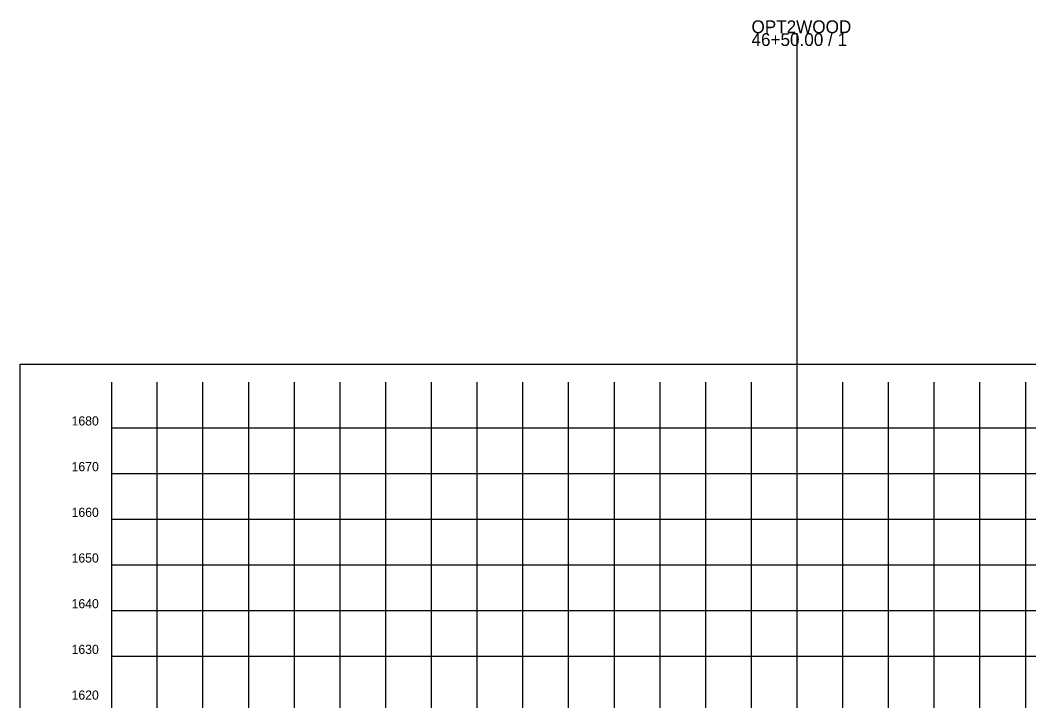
# Model space of a CAD drawing. Extents: x -26 to 2998798, y -429 to 819149.
# Drawn here: x 130 to 350.7, y 2089.2 to 2238.2 of the extents above; entities that cross this region are included whole.
import ezdxf

# ---------------------------------------------------------------- set-up
doc = ezdxf.new("R2010")
doc.units = 0
for name, color, linetype in [('DESIGN - SHEET - Corner Text', 7, 'Continuous'), ('DESIGN - SHEET - Light Grid', 7, 'Continuous'), ('DESIGN - SHEET - Linework', 7, 'Continuous'), ('DESIGN - SHEET - Plot Shape', 7, 'Continuous')]:
    doc.layers.add(name, color=color, linetype=linetype)

msp = doc.modelspace()

# ---------------------------------------------------------------- linework, layer by layer
at = {"layer": 'DESIGN - SHEET - Light Grid'}
msp.add_line((300, 2000), (300, 2235.37), dxfattribs=at)
at = {"layer": 'DESIGN - SHEET - Linework'}
for p, q in [((160, 1949), (160, 2159)), ((170, 1949), (170, 2159)), ((180, 1949), (180, 2159)), ((190, 1949), (190, 2159)), ((200, 1949), (200, 2159)), ((210, 1949), (210, 2159)), ((220, 1949), (220, 2159)), ((230, 1949), (230, 2159)), ((240, 1949), (240, 2159)), ((250, 1949), (250, 2159)), ((260, 1949), (260, 2159)), ((270, 1949), (270, 2159)), ((280, 1949), (280, 2159)), ((290, 1949), (290, 2159)), ((300, 1949), (300, 2159)), ((310, 1949), (310, 2159)), ((320, 1949), (320, 2159)), ((330, 1949), (330, 2159)), ((340, 1949), (340, 2159)), ((350, 1949), (350, 2159)), ((150, 2149), (450, 2149)), ((150, 2139), (450, 2139)), ((150, 2129), (450, 2129)), ((150, 2119), (450, 2119)), ((150, 2109), (450, 2109)), ((150, 2099), (450, 2099))]:
    msp.add_line(p, q, dxfattribs=at)
msp.add_lwpolyline([(150, 2159), (150, 1949), (450, 1949), (450, 2159)], dxfattribs=at)
at = {"layer": 'DESIGN - SHEET - Plot Shape'}
msp.add_lwpolyline([(130, 2162.94), (470, 2162.94), (470, 1945.06), (130, 1945.06)], close=True, dxfattribs=at)

# ---------------------------------------------------------------- texts
at = {"layer": 'DESIGN - SHEET - Corner Text'}
for s, p in [('1680', (141.25, 2149.5)), ('1670', (141.25, 2139.5)), ('1660', (141.25, 2129.5)), ('1650', (141.25, 2119.5)), ('1640', (141.25, 2109.5)), ('1630', (141.25, 2099.5)), ('1620', (141.25, 2089.5))]:
    msp.add_text(s, height=2, dxfattribs=at).set_placement(p)
at = {"layer": 'DESIGN - SHEET - Light Grid'}
for s, p in [('OPT2WOOD', (290, 2235.37)), ('46+50.00 / 1', (290, 2232.57))]:
    msp.add_text(s, height=2.8, dxfattribs=at).set_placement(p)

doc.saveas('drawing.dxf')
